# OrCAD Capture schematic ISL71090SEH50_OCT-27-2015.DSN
size A
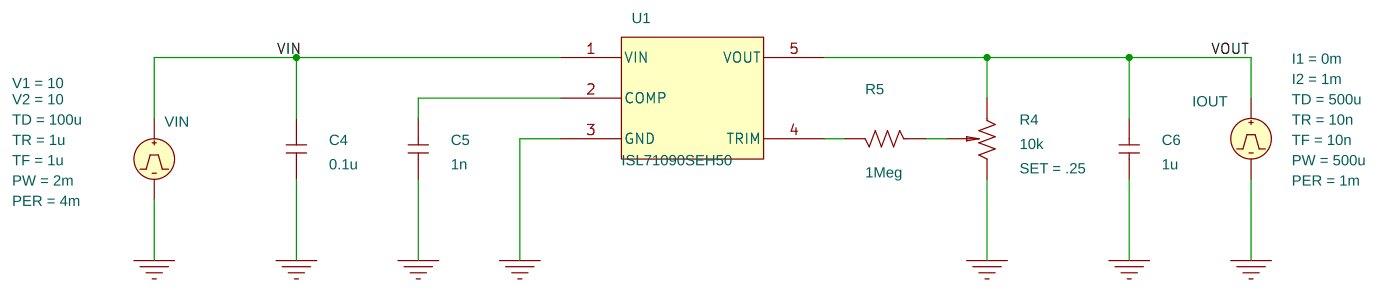
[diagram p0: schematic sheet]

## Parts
C4  0.1u  [RAD/CK05]
C5  1n  [RAD/CK05]
C6  1u  [RAD/CK05]
IOUT  IPULSE
R4  10k  [VRES10]
R5  1Meg  [AX/RC05]
U1  ISL71090SEH50
VIN  VPULSE

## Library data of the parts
C4-C6 = C
IOUT = IPULSE: I1: 0m; I2: 1m; PER: 1m; PW: 500u; TD: 500u; TF: 10n; TR: 10n
R4 = POT: SET: .25
R5 = R
U1 = ISL71090SEH50
VIN = VPULSE: PER: 4m; PW: 2m; TD: 100u; TF: 1u; TR: 1u; V1: 10; V2: 10

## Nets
VIN: C4.2 U1.1(VIN) VIN.1(+)
0: C4.1 C5.1 C6.1 IOUT.2(-) R4.3(2) U1.3(GND) VIN.2(-)
VOUT: C6.2 IOUT.1(+) R4.1 U1.5(VOUT)
N16318: C5.2 U1.2(COMP)
N18691: R5.2 U1.4(TRIM)
N18907: R4.2(t) R5.1
